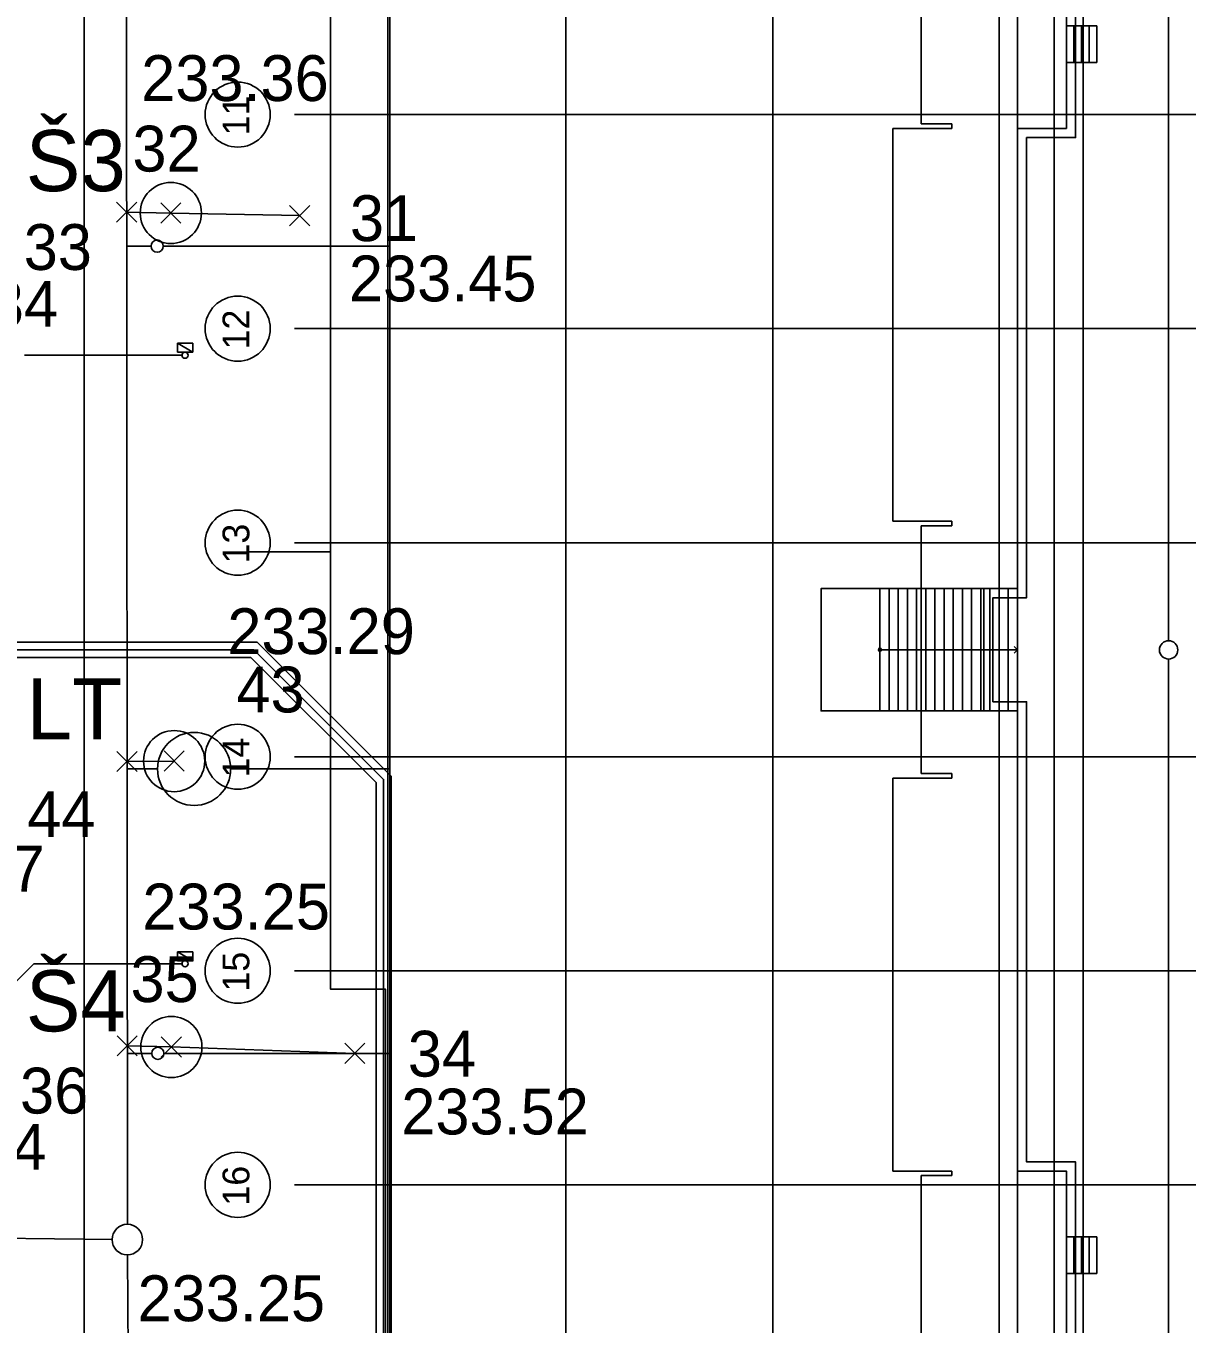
# Model space of a CAD drawing. Extents: x -264031 to -263588, y -1242281 to -1242059.
# Drawn here: x -263926.05 to -263888.07, y -1242186.43 to -1242143.98 of the extents above; entities that cross this region are included whole.
import ezdxf

# ---------------------------------------------------------------- set-up
doc = ezdxf.new("R2010")
doc.units = 0
for name, color, linetype in [('HESCON_OSI_STAVBY_KFA', 7, 'Continuous'), ('KFA_2D_SITUACIA_DSP', 7, 'Continuous'), ('KFA_BODY_CISLO', 7, 'Continuous'), ('KFA_BODY_SYMBOL', 7, 'Continuous'), ('KFA_BODY_VYSKA', 7, 'Continuous'), ('KFA_JESTV_IS_DSP_-_KANAL_SPLASK', 7, 'Continuous'), ('KFA_SO-40-1-II_SK_MER_TRIBUNA_A', 7, 'Continuous'), ('POPIS', 7, 'Continuous')]:
    doc.layers.add(name, color=color, linetype=linetype)

msp = doc.modelspace()

# ---------------------------------------------------------------- linework, layer by layer
at = {"layer": 'HESCON_OSI_STAVBY_KFA'}
for p, q in [((-263908.393, -1242083.237), (-263908.393, -1242246.707)), ((-263901.618, -1242083.237), (-263901.618, -1242246.707)), ((-263894.218, -1242083.237), (-263894.218, -1242246.707)), ((-263892.418, -1242083.237), (-263892.418, -1242246.707)), ((-263891.468, -1242083.237), (-263891.468, -1242246.707)), ((-263917.265, -1242146.882), (-263905.505, -1242146.882)), ((-263917.265, -1242146.882), (-263905.505, -1242146.882)), ((-263792.653, -1242146.882), (-263909.343, -1242146.882)), ((-263917.265, -1242153.882), (-263905.505, -1242153.882)), ((-263917.265, -1242153.882), (-263905.505, -1242153.882)), ((-263792.653, -1242153.882), (-263909.343, -1242153.882)), ((-263917.265, -1242160.882), (-263905.505, -1242160.882)), ((-263917.265, -1242160.882), (-263905.505, -1242160.882)), ((-263792.653, -1242160.882), (-263909.343, -1242160.882)), ((-263917.265, -1242167.882), (-263905.505, -1242167.882)), ((-263917.265, -1242167.882), (-263905.505, -1242167.882)), ((-263792.653, -1242167.882), (-263909.343, -1242167.882)), ((-263917.265, -1242174.882), (-263905.505, -1242174.882)), ((-263917.265, -1242174.882), (-263905.505, -1242174.882)), ((-263792.653, -1242174.882), (-263909.343, -1242174.882)), ((-263917.265, -1242181.882), (-263905.505, -1242181.882)), ((-263917.265, -1242181.882), (-263905.505, -1242181.882)), ((-263792.653, -1242181.882), (-263909.343, -1242181.882))]:
    msp.add_line(p, q, dxfattribs=at)
for centre in [(-263919.125, -1242146.882), (-263919.125, -1242153.882), (-263919.125, -1242160.882), (-263919.125, -1242167.882), (-263919.125, -1242174.882), (-263919.125, -1242181.882)]:
    msp.add_circle(centre, 1.064, dxfattribs=at)
at = {"layer": 'KFA_2D_SITUACIA_DSP'}
for p, q in [((-263924.143, -1242082.64), (-263924.143, -1242185.14)), ((-263888.673, -1242108.177), (-263888.673, -1242164.087)), ((-263896.768, -1242125.432), (-263896.768, -1242147.182)), ((-263914.218, -1242196.332), (-263914.218, -1242132.432)), ((-263892.018, -1242143.983), (-263891.018, -1242143.983)), ((-263891.768, -1242143.983), (-263891.768, -1242145.181)), ((-263891.518, -1242143.983), (-263891.518, -1242145.181)), ((-263891.268, -1242143.983), (-263891.268, -1242145.181)), ((-263891.018, -1242143.983), (-263891.018, -1242145.181)), ((-263891.018, -1242145.181), (-263892.018, -1242145.181)), ((-263895.768, -1242147.332), (-263897.693, -1242147.332)), ((-263897.693, -1242147.332), (-263897.693, -1242160.182)), ((-263896.768, -1242147.182), (-263895.768, -1242147.182)), ((-263895.768, -1242147.182), (-263895.768, -1242147.332)), ((-263921.957, -1242151.182), (-263922.757, -1242151.182)), ((-263917.093, -1242151.182), (-263921.557, -1242151.182)), ((-263914.143, -1242151.182), (-263917.093, -1242151.182)), ((-263921.093, -1242154.652), (-263921.093, -1242154.362)), ((-263921.093, -1242154.362), (-263920.593, -1242154.362)), ((-263920.593, -1242154.652), (-263921.093, -1242154.362)), ((-263920.593, -1242154.652), (-263921.093, -1242154.362)), ((-263921.093, -1242154.362), (-263921.093, -1242154.652)), ((-263920.593, -1242154.652), (-263921.093, -1242154.652)), ((-263921.093, -1242154.652), (-263920.593, -1242154.652)), ((-263920.593, -1242154.362), (-263920.593, -1242154.652)), ((-263920.944, -1242154.752), (-263926.093, -1242154.752)), ((-263897.693, -1242160.182), (-263895.768, -1242160.182)), ((-263895.768, -1242160.182), (-263895.768, -1242160.332)), ((-263895.768, -1242160.332), (-263896.768, -1242160.332)), ((-263896.768, -1242160.332), (-263896.768, -1242168.432)), ((-263916.093, -1242161.182), (-263918.763, -1242161.182)), ((-263898.118, -1242162.382), (-263898.118, -1242166.382)), ((-263897.818, -1242162.382), (-263897.818, -1242166.382)), ((-263897.518, -1242162.382), (-263897.518, -1242166.382)), ((-263897.218, -1242162.382), (-263897.218, -1242166.382)), ((-263896.918, -1242162.382), (-263896.918, -1242166.382)), ((-263896.618, -1242162.382), (-263896.618, -1242166.382)), ((-263896.318, -1242162.382), (-263896.318, -1242166.382)), ((-263896.018, -1242162.382), (-263896.018, -1242166.382)), ((-263895.718, -1242162.382), (-263895.718, -1242166.382)), ((-263895.418, -1242162.382), (-263895.418, -1242166.382)), ((-263895.118, -1242162.382), (-263895.118, -1242166.382)), ((-263894.818, -1242162.382), (-263894.818, -1242166.382)), ((-263894.518, -1242162.382), (-263894.518, -1242166.382)), ((-263894.218, -1242162.382), (-263894.218, -1242166.382)), ((-263893.918, -1242162.382), (-263893.918, -1242166.382)), ((-263893.618, -1242162.382), (-263893.618, -1242166.382)), ((-263918.489, -1242164.132), (-263946.093, -1242164.132)), ((-263918.593, -1242164.382), (-263946.093, -1242164.382)), ((-263898.118, -1242164.382), (-263893.618, -1242164.382)), ((-263893.618, -1242164.382), (-263893.721, -1242164.274)), ((-263893.618, -1242164.382), (-263893.721, -1242164.491)), ((-263918.696, -1242164.632), (-263946.093, -1242164.632)), ((-263888.673, -1242164.687), (-263888.673, -1242220.396)), ((-263922.745, -1242168.282), (-263921.745, -1242168.282)), ((-263914.143, -1242168.282), (-263919.355, -1242168.282)), ((-263895.768, -1242168.582), (-263897.693, -1242168.582)), ((-263897.693, -1242168.582), (-263897.693, -1242181.432)), ((-263896.768, -1242168.432), (-263895.768, -1242168.432)), ((-263895.768, -1242168.432), (-263895.768, -1242168.582)), ((-263921.093, -1242174.553), (-263921.093, -1242174.263)), ((-263921.093, -1242174.263), (-263920.593, -1242174.263)), ((-263920.593, -1242174.553), (-263921.093, -1242174.263)), ((-263920.593, -1242174.553), (-263921.093, -1242174.263)), ((-263921.093, -1242174.263), (-263921.093, -1242174.553)), ((-263920.593, -1242174.553), (-263921.093, -1242174.553)), ((-263921.093, -1242174.553), (-263920.593, -1242174.553)), ((-263920.593, -1242174.263), (-263920.593, -1242174.553)), ((-263925.798, -1242174.653), (-263926.593, -1242175.448)), ((-263920.944, -1242174.653), (-263925.798, -1242174.653)), ((-263921.938, -1242177.582), (-263922.738, -1242177.582)), ((-263915.293, -1242177.582), (-263921.538, -1242177.582)), ((-263914.143, -1242177.582), (-263915.293, -1242177.582)), ((-263897.693, -1242181.432), (-263895.768, -1242181.432)), ((-263895.768, -1242181.582), (-263896.768, -1242181.582)), ((-263896.768, -1242181.582), (-263896.768, -1242203.332)), ((-263895.768, -1242181.432), (-263895.768, -1242181.582)), ((-263892.018, -1242183.583), (-263891.018, -1242183.583)), ((-263891.768, -1242183.583), (-263891.768, -1242184.781)), ((-263891.518, -1242183.583), (-263891.518, -1242184.781)), ((-263891.268, -1242183.583), (-263891.268, -1242184.781)), ((-263891.018, -1242183.583), (-263891.018, -1242184.781)), ((-263891.018, -1242184.781), (-263892.018, -1242184.781)), ((-263924.143, -1242185.14), (-263924.143, -1242250.14))]:
    msp.add_line(p, q, dxfattribs=at)
for points in [[(-263794.893, -1242227.382), (-263808.968, -1242241.457), (-263894.968, -1242241.457), (-263909.043, -1242227.382), (-263909.043, -1242196.333), (-263914.143, -1242196.333), (-263914.143, -1242132.433), (-263909.043, -1242132.433), (-263909.043, -1242101.382), (-263894.968, -1242087.307), (-263808.968, -1242087.307), (-263794.893, -1242101.382), (-263794.893, -1242227.382)], [(-263816.02, -1242224.432), (-263887.916, -1242224.432), (-263888.26, -1242224.088), (-263889.254, -1242226.488), (-263890.391, -1242225.351), (-263894.351, -1242229.311), (-263896.896, -1242226.765), (-263892.937, -1242222.806), (-263894.073, -1242221.669), (-263891.673, -1242220.675), (-263892.018, -1242220.33), (-263892.018, -1242181.432), (-263893.618, -1242181.432), (-263893.618, -1242147.332), (-263892.018, -1242147.332), (-263892.018, -1242108.434)], [(-263918.593, -1242164.382), (-263914.35, -1242168.625), (-263914.35, -1242199.59), (-263910.108, -1242203.832), (-263891.768, -1242203.832)], [(-263918.489, -1242164.132), (-263914.1, -1242168.521), (-263914.1, -1242199.486), (-263910.004, -1242203.582), (-263891.768, -1242203.582)], [(-263918.696, -1242164.632), (-263914.6, -1242168.728), (-263914.6, -1242199.693), (-263910.211, -1242204.082), (-263891.768, -1242204.082)]]:
    msp.add_lwpolyline(points, dxfattribs=at)
for points in [[(-263816.02, -1242224.432), (-263811.918, -1242220.33), (-263811.918, -1242108.434), (-263816.02, -1242104.332), (-263887.916, -1242104.332), (-263892.018, -1242108.434), (-263892.018, -1242147.332), (-263893.618, -1242147.332), (-263893.618, -1242162.382), (-263894.718, -1242162.382), (-263894.718, -1242166.382), (-263893.618, -1242166.382), (-263893.618, -1242181.432), (-263892.018, -1242181.432), (-263892.018, -1242220.33), (-263887.916, -1242224.432)], [(-263816.144, -1242224.132), (-263812.218, -1242220.206), (-263812.218, -1242108.558), (-263816.144, -1242104.632), (-263887.792, -1242104.632), (-263891.718, -1242108.558), (-263891.718, -1242147.632), (-263893.318, -1242147.632), (-263893.318, -1242162.682), (-263894.418, -1242162.682), (-263894.418, -1242166.082), (-263893.318, -1242166.082), (-263893.318, -1242181.132), (-263891.718, -1242181.132), (-263891.718, -1242220.206), (-263887.792, -1242224.132)], [(-263893.618, -1242118.282), (-263916.093, -1242118.282), (-263916.093, -1242175.482), (-263914.293, -1242175.482), (-263914.293, -1242210.482), (-263893.618, -1242210.482), (-263893.618, -1242166.382), (-263900.043, -1242166.382), (-263900.043, -1242162.382), (-263893.618, -1242162.382)]]:
    msp.add_lwpolyline(points, close=True, dxfattribs=at)
for centre, radius in [((-263921.757, -1242151.182), 0.2), ((-263920.844, -1242154.752), 0.1), ((-263898.118, -1242164.382), 0.05), ((-263888.673, -1242164.387), 0.3), ((-263920.55, -1242168.282), 1.195), ((-263920.844, -1242174.653), 0.1), ((-263921.738, -1242177.582), 0.2)]:
    msp.add_circle(centre, radius, dxfattribs=at)
at = {"layer": 'KFA_BODY_SYMBOL'}
for p, q in [((-263923.088, -1242150.404), (-263922.425, -1242149.741)), ((-263922.425, -1242150.404), (-263923.088, -1242149.741)), ((-263921.643, -1242150.433), (-263920.98, -1242149.769)), ((-263920.98, -1242150.433), (-263921.643, -1242149.769)), ((-263917.425, -1242150.514), (-263916.762, -1242149.85)), ((-263916.762, -1242150.514), (-263917.425, -1242149.85)), ((-263923.077, -1242168.37), (-263922.414, -1242167.707)), ((-263922.414, -1242168.37), (-263923.077, -1242167.707)), ((-263921.534, -1242168.356), (-263920.871, -1242167.694)), ((-263920.871, -1242168.356), (-263921.534, -1242167.694)), ((-263923.071, -1242177.667), (-263922.408, -1242177.005)), ((-263922.408, -1242177.667), (-263923.071, -1242177.005)), ((-263921.625, -1242177.705), (-263920.962, -1242177.042)), ((-263920.962, -1242177.705), (-263921.625, -1242177.042)), ((-263915.625, -1242177.914), (-263914.962, -1242177.251)), ((-263914.962, -1242177.914), (-263915.625, -1242177.251))]:
    msp.add_line(p, q, dxfattribs=at)
at = {"layer": 'KFA_JESTV_IS_DSP_-_KANAL_SPLASK'}
for p, q in [((-263922.763, -1242141.975), (-263922.734, -1242183.174)), ((-263923.234, -1242183.668), (-263965.273, -1242183.165)), ((-263922.479, -1242221.753), (-263922.731, -1242184.174))]:
    msp.add_line(p, q, dxfattribs=at)
msp.add_circle((-263922.734, -1242183.674), 0.5, dxfattribs=at)
at = {"layer": 'KFA_SO-40-1-II_SK_MER_TRIBUNA_A'}
msp.add_line((-263921.203, -1242168.025), (-263922.745, -1242168.038), dxfattribs=at)
for points in [[(-263917.093, -1242150.182), (-263921.312, -1242150.101), (-263922.757, -1242150.072)], [(-263915.293, -1242177.582), (-263921.293, -1242177.374), (-263922.739, -1242177.336)]]:
    msp.add_lwpolyline(points, dxfattribs=at)
for centre in [(-263921.312, -1242150.101), (-263921.203, -1242168.025), (-263921.293, -1242177.374)]:
    msp.add_circle(centre, 1, dxfattribs=at)

# ---------------------------------------------------------------- texts
at = {"layer": 'HESCON_OSI_STAVBY_KFA'}
for s, p in [('11', (-263918.744, -1242147.562)), ('12', (-263918.744, -1242154.562)), ('13', (-263918.744, -1242161.562)), ('14', (-263918.744, -1242168.562)), ('15', (-263918.744, -1242175.562)), ('16', (-263918.744, -1242182.562))]:
    msp.add_text(s, height=0.875, rotation=90, dxfattribs=at).set_placement(p)
at = {"layer": 'KFA_BODY_CISLO'}
for s, p in [('32', (-263922.567, -1242148.744)), ('31', (-263915.453, -1242151.019)), ('33', (-263926.124, -1242151.963)), ('43', (-263919.166, -1242166.433)), ('44', (-263926.01, -1242170.512)), ('35', (-263922.631, -1242175.905)), ('34', (-263913.56, -1242178.344)), ('36', (-263926.246, -1242179.551))]:
    msp.add_text(s, height=1.5, dxfattribs=at).set_placement(p)
at = {"layer": 'KFA_BODY_VYSKA'}
for s, p in [('233.36', (-263922.281, -1242146.438)), ('233.45', (-263915.486, -1242152.99)), ('233.34', (-263931.135, -1242153.82)), ('233.29', (-263919.464, -1242164.527)), ('233.27', (-263931.576, -1242172.291)), ('233.25', (-263922.242, -1242173.532)), ('233.52', (-263913.773, -1242180.235)), ('233.24', (-263931.514, -1242181.388)), ('233.25', (-263922.402, -1242186.342))]:
    msp.add_text(s, height=1.5, dxfattribs=at).set_placement(p)
at = {"layer": 'POPIS'}
for s, p in [('Š3', (-263926.057, -1242149.386)), ('LT', (-263926.027, -1242167.314)), ('Š4', (-263926.055, -1242176.864))]:
    msp.add_text(s, height=2, dxfattribs=at).set_placement(p)

doc.saveas('drawing.dxf')
